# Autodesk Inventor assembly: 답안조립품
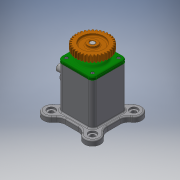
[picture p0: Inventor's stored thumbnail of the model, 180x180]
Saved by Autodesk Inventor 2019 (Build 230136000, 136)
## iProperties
Created: 2021-01
Part Number: 답안조립품
Material: 일반
Document SubType Name: Assembly
Designer: 3DPRO3
Author: 3DPRO3
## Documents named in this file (11)
- C:\Users\3DPRO3\Desktop\710114V1011\답안조립품.iam
- C:\Users\3DPRO3\Desktop\710114V1011\본체.ipt
- C:\Users\3DPRO3\Desktop\710114V1011\베어링 6203.ipt
- C:\Users\3DPRO3\Desktop\710114V1011\볼트 M4.ipt
- C:\Users\3DPRO3\Desktop\710114V1011\부시.ipt
- C:\Users\3DPRO3\Desktop\710114V1011\스퍼기어.ipt
- C:\Users\3DPRO3\Desktop\710114V1011\슬라이더.ipt
- C:\Users\3DPRO3\Desktop\710114V1011\오일 실.ipt
- C:\Users\3DPRO3\Desktop\710114V1011\커버.ipt
- C:\Users\3DPRO3\Desktop\710114V1011\키 4 x 4 x 14.ipt
- C:\Users\3DPRO3\Desktop\710114V1011\편심축.ipt
